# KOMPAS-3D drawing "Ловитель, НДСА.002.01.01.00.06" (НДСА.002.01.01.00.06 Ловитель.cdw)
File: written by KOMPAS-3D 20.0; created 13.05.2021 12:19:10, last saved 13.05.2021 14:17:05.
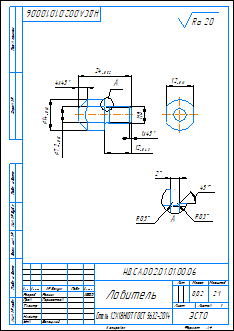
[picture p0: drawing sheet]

Sheet 1: A4, portrait

Document properties: Параметр неуказанной шероховатости: Ra 20; PLM_CDWXDTO: <item xmlns="http://appius.ru/pdm" xmlns:xs="http://www.w3.org/2001/XMLSchema" xmlns:xsi="http://www.w3.org/2001/XMLSchema-instance" xsi:type="item">  <element xmlns:d2p1="http://v8.1c.ru/8.1/data/enterprise/current-config" xsi:type="d2p1:CatalogRef.aps_Элемен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; Масса: 0.02; Полное имя файла: НДСА.002.01.01.00.06 Ловитель.m3d; Автор: Пользователь Windows

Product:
- Part/product: Ловитель  | designation НДСА.002.01.01.00.06
    Материал: Сталь 12Х18Н10Т ГОСТ 5632-2014 (density 7900 kg/m3)
    Масса: 0.0162591
    additional columns: <item xmlns="http://appius.ru/pdm" xmlns:xs="http://www.w3.org/2001/XMLSchema" x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; <item xmlns="http://appius.ru/pdm" xmlns:xs="http://www.w3.org/2001/XMLSchema" x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; <item xmlns="http://appius.ru/pdm" xmlns:xs="http://www.w3.org/2001/XMLSchema" x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; <item xmlns="http://appius.ru/pdm" xmlns:xs="http://www.w3.org/2001/XMLSchema" x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; <item xmlns="http://appius.ru/pdm" xmlns:xs="http://www.w3.org/2001/XMLSchema" x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; <item xmlns="http://appius.ru/pdm" xmlns:xs="http://www.w3.org/2001/XMLSchema" x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; <item xmlns="http://appius.ru/pdm" xmlns:xs="http://www.w3.org/2001/XMLSchema" x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; <item xmlns="http://appius.ru/pdm" xmlns:xs="http://www.w3.org/2001/XMLSchema" x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
    source file: НДСА.002.01.01.00.06 Ловитель.cdw

Title block, sheet 1: Наименование: Ловитель; designation: НДСА.002.01.01.00.06; Материал: Сталь 12Х18Н10Т ГОСТ 5632-2014; Масса: 0,02; scale: 2:1; Количество листов документа: 1; organisation: ЭСТО; Форматы листов документа: A4; stored path: D:\Работа Артём\НДСА.002.17.00.00.00 Система водяного охлаждения\НДСА.002.01.01.00.06 Ловитель.cdw; Разработал: Резник; Проверил: Горностаев; Утвердил: Белецкий; Разработал, date: 11.05.2021

Views: Вид 1, Вид 2, Снизу, Проекционный вид 3, Выносной элемент 4, Выносной элемент А, Выносной элемент
Referenced files in D:\Работа Артём\НДСА.002.17.00.00.00 Система водяного охлаждения\: НДСА.002.01.01.00.06 Ловитель.m3d
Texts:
  Ra 20
  НДСА.002.01.01.00.06 Ловитель
Dimensions and other numbers on the sheet: 7,2; 14; 24; 4; 12; 8; 1; 0,5; 0,3; 2; 2:1; 0,02; 11.05.2021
